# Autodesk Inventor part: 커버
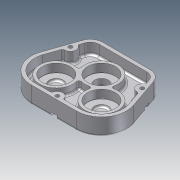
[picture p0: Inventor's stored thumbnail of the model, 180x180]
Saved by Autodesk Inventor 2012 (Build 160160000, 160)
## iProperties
Company: 한국ATC센터
Created: 2014-12
Part Number: 커버
Document SubType Name: Modeling
Designer: KYOUNG IL JANG
Density: 1 g/cm^3
Mass: 160.364 g
Surface Area: 512.085 cm^2
Volume: 160.364 cm^3
Material: 기본값
Author: KYOUNG IL JANG
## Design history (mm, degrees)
sketch "스케치1"
  geometry: L1 (-66.565, -20.803)-(-47, 36); L2 (47, 36)-(66.565, -20.803); L3 (-32.527, -68.527)-(32.527, -68.527); L4 (-47, 36)-(47, 36); C1 r 28 at (0, 0); C2 r 18 at (-32.527, -32.527); C3 r 18 at (32.527, -32.527); A1 r 36 centre (-32.527, -32.527) between (-66.565, -20.803) and (-32.527, -68.527); A2 r 36 centre (32.527, -32.527) between (32.527, -68.527) and (66.565, -20.803); 2 further points
  constraints: 8 end point, 6 tangent, 5 centre point, 4 point on circle, 3 coincident, 2 equal radius, 1 equal length, 1 horizontal alignment, 1 midpoint, 1 vertical alignment
  dimensions: "d0" = 56 diameter of C1; "d1" = 36 diameter of C2; "d2" = 90 deg dimension on point (0, 0) C3.centre C2.centre; "d3" = 36 radius of A1; "d4" = 104.52691 distance between parallel lines of L3 L4 (derived); "d5" = 94 distance of L1.end L2.start; "d65" = 36 distance from line of point (0, 0) L4
extrude "돌출1" new body sketch "스케치1" distance "d6" = 25; taper "d7" = 0 deg
fillet "모깎기1" dims "d8" = 18
feature "쉘1" dims "d9" = 9, "d10" = 5
sketch "스케치2"
  geometry: C1 r 24 at (1.635, -63.527); C2 r 24 at (66.689, -63.527); C3 r 24 at (34.162, -31); 4 further points
  constraints: 4 coincident, 3 centre point, 1 equal radius
  dimensions: "d11" = 48 diameter of C3; "d12" = 48 diameter of C2
extrude "돌출2" join sketch "스케치2" distance "d13" = 11; taper "d14" = 0 deg
hole "구멍1" diameter "d17" = 20; stored, may be unused: countersink angle "d21" = 90 deg, drill point angle "d23" = 0 deg; dims "d15" = 10, "d16" = 10, "d18" = 6, "d19" = 40, "d20" = 12, "d22" = 3
hole "구멍2" diameter "d26" = 20; stored, may be unused: countersink angle "d30" = 90 deg, drill point angle "d32" = 0 deg; dims "d24" = 10, "d25" = 10, "d27" = 6, "d28" = 40, "d29" = 12, "d31" = 3
hole "구멍3" diameter "d35" = 20; stored, may be unused: countersink angle "d39" = 90 deg, drill point angle "d41" = 118 deg; dims "d33" = 10, "d34" = 10, "d36" = 6, "d37" = 40, "d38" = 12, "d40" = 3
sketch "스케치3"
  geometry: C1 r 15 at (0, 0); C2 r 20 at (0, 0); 1 further point
  constraints: 2 centre point, 2 coincident
  dimensions: "d42" = 40 diameter of C2; "d43" = 30 diameter of C1
extrude "돌출3" join sketch "스케치3" distance "d44" = 8; taper "d45" = 0 deg
feature "면 기울기1" dims angle "d46" = 10 deg
fillet "모깎기2" dims "d47" = 3
fillet "모깎기3" dims "d48" = 0.3
fillet "모깎기6" dims "d66" = 0.1
sketch "스케치4"
  geometry: L1 (-61.837, -22.432)-(-46.453, 22.233) reference; L2 (46.453, 22.233)-(61.837, -22.432) reference; L3 (32.527, -63.527)-(-32.527, -63.527) reference; L4 (-34.162, 31)-(34.162, 31) reference; A1 r 8 centre (51.7, 7) between (49.095, 14.564) and (54.305, -0.564); A2 r 8 centre (-51.7, 7) between (-54.305, -0.564) and (-49.095, 14.564); A3 r 8 centre (0, -63.527) between (8, -63.527) and (-8, -63.527)
  constraints: 8 point on line, 6 point on circle, 3 centre point, 2 equal radius, 1 horizontal alignment, 1 midpoint
  dimensions: "d49" = 8 radius of A1; "d51" = 24 distance from line of A2.centre L4
extrude "돌출4" join sketch "스케치4" stored distance "d52" = 8; taper "d53" = 0 deg
fillet "모깎기4" dims "d54" = 3
sketch "스케치5"
  geometry: A1 r 8 centre (-51.7, 7) between (-52.144, -0.988) and (-47.131, 13.567) reference; A2 r 8 centre (0, -63.527) between (7.697, -61.345) and (-7.697, -61.345) reference; A3 r 8 centre (51.7, 7) between (47.131, 13.567) and (52.144, -0.988) reference; 1 further point
hole "구멍4" sketch "스케치5" at (0, -63.527), (-51.7, 7), (51.7, 7) diameter "d55" = 5.5; stored, may be unused: countersink angle "d59" = 90 deg, drill point angle "d61" = 118 deg; dims "d56" = 6, "d57" = 9.5, "d58" = 5.4, "d60" = 3
sketch "스케치6"
  geometry: L1 (-51.181, 23.862)-(-66.565, -20.803) reference; L2 (66.565, -20.803)-(51.181, 23.862) reference; L3 (-32.527, -68.527)-(32.527, -68.527) reference; L4 (-50.153, 11.491)-(-54.881, 13.119); L5 (-53.247, 2.509)-(-57.974, 4.137); L6 (50.153, 11.491)-(54.881, 13.119); L7 (53.247, 2.509)-(57.974, 4.137); L8 (4.75, -63.527)-(4.75, -68.527); L9 (-4.75, -63.527)-(-4.75, -68.527); A1 r 4.75 centre (-51.7, 7) between (-54.994, 3.578) and (-52.188, 11.725) reference; A2 r 4.75 centre (51.7, 7) between (52.188, 11.725) and (54.994, 3.578) reference; A3 r 4.75 centre (0, -63.527) between (4.308, -65.527) and (-4.308, -65.527) reference; 1 further point
  constraints: 12 end point, 6 perpendicular, 6 point on circle, 6 point on line, 6 tangent
extrude "돌출5" cut sketch "스케치6" distance "d62" = 5.4; taper "d63" = 0 deg
fillet "모깎기5" dims "d64" = 3
node "솔리드1"
